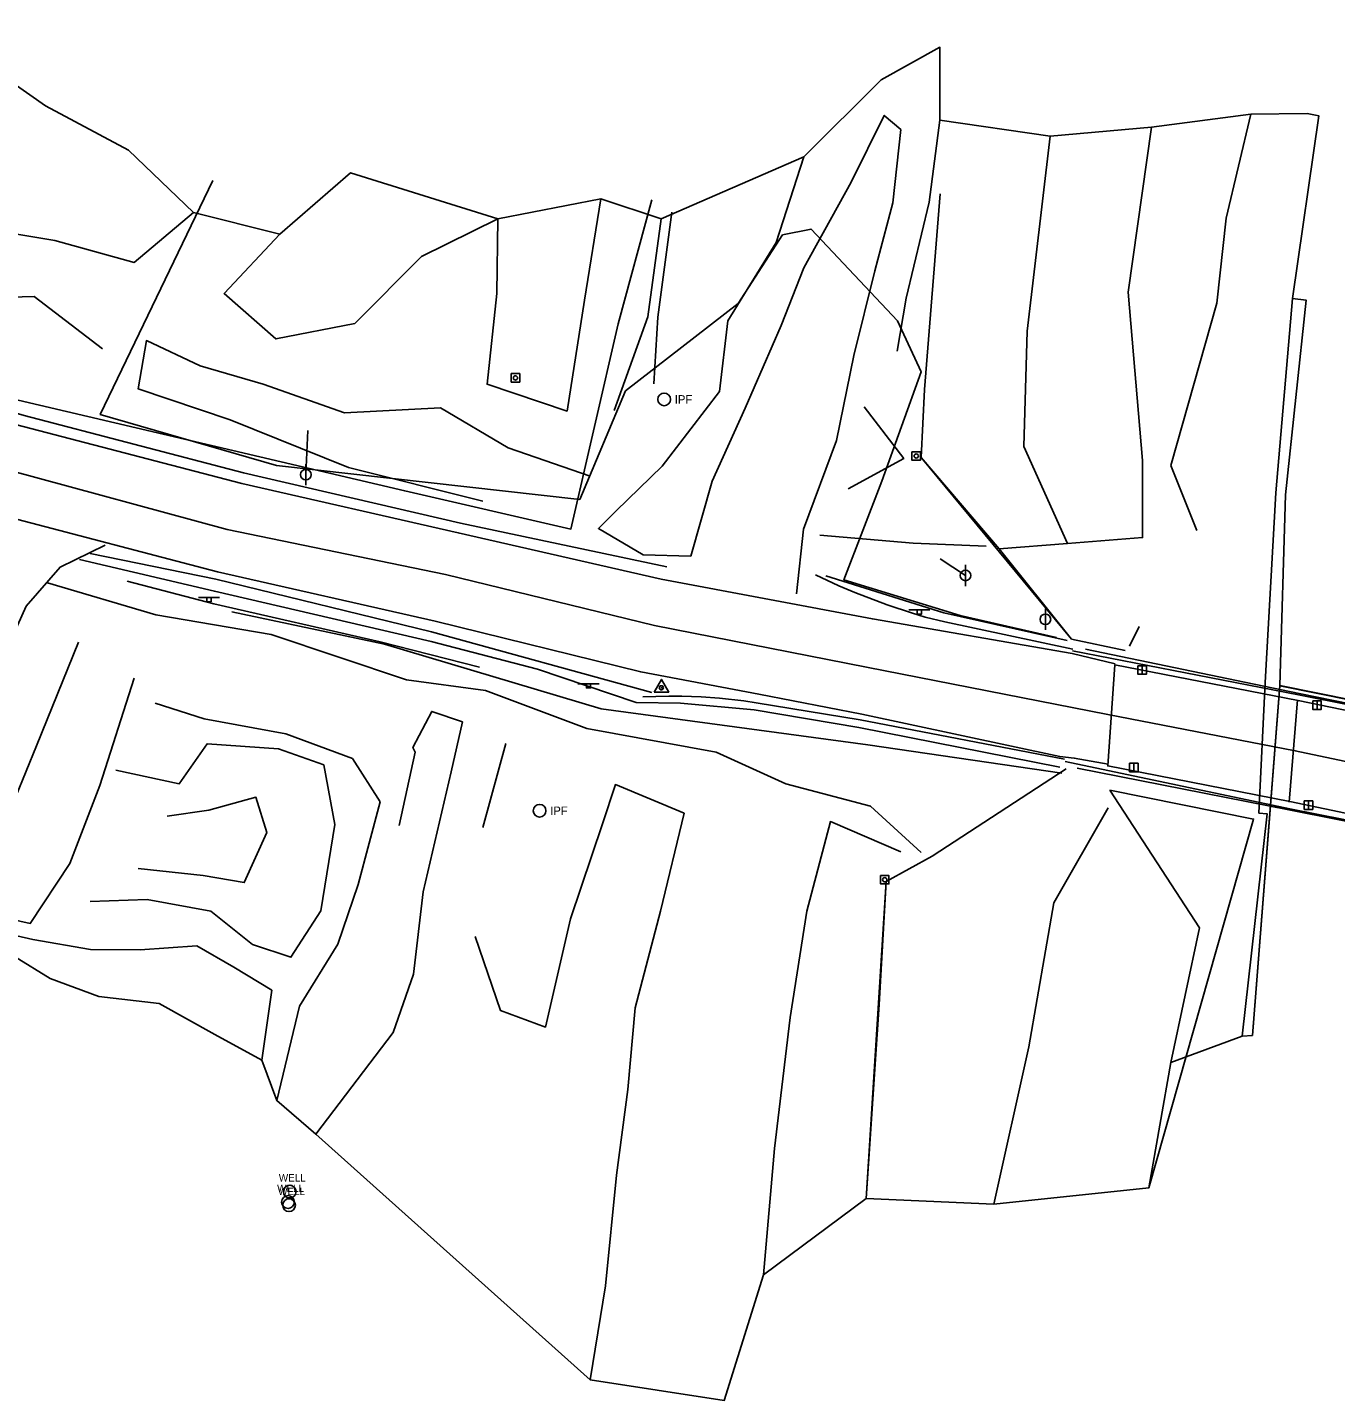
# Model space of a CAD drawing. Extents: x 1158469 to 1165378, y 609843 to 611748.
# Drawn here: x 1159076.5 to 1159385.7, y 611115.2 to 611439.6 of the extents above; entities that cross this region are included whole.
import ezdxf

# ---------------------------------------------------------------- set-up
doc = ezdxf.new("R2010")
doc.units = 0
for name, color, linetype in [('Exterior Boundary', 7, 'Continuous'), ('S_Bridge_Centerline', 7, 'Continuous'), ('S_Bridge_Curb', 7, 'Continuous'), ('S_Bridge_Deck', 7, 'Continuous'), ('S_Bridge_Downspout', 7, 'Continuous'), ('S_Bridge_ExpansionJoint', 7, 'Continuous'), ('S_Bridge_Rail', 7, 'Continuous'), ('S_Control_Temp_Traverse', 7, 'Continuous'), ('S_Fencing_PostAndRail', 7, 'Continuous'), ('S_Fencing_SmoothWire', 7, 'Continuous'), ('S_Ground_Elevation', 7, 'Continuous'), ('S_Guardrail_Beam', 7, 'Continuous'), ('S_Property_IronPipeFound', 7, 'Continuous'), ('S_Property_StoneWall', 7, 'Continuous'), ('S_Property_Well_Top', 7, 'Continuous'), ('S_Roadway_Centerline', 7, 'Continuous'), ('S_Roadway_Drive_Gravel', 7, 'Continuous'), ('S_Roadway_Edge_Pavement', 7, 'Continuous'), ('S_Roadway_Edge_Shoulder', 7, 'Continuous'), ('S_Roadway_Monument', 7, 'Continuous'), ('S_Traffic_Sign_SinglePost', 7, 'Continuous'), ('S_Trees_TreeLine', 7, 'Continuous'), ('S_Utilities_GuyWire3', 7, 'Continuous'), ('S_Utilities_Pole_Power', 7, 'Continuous')]:
    doc.layers.add(name, color=color, linetype=linetype)

msp = doc.modelspace()

# ---------------------------------------------------------------- linework, layer by layer
at = {"layer": 'Exterior Boundary'}
for points in [[(1159635.63, 611231.07), (1159372.54, 611284.19), (1159373.88, 611329.19), (1159378.74, 611375.17), (1159375.51, 611375.57), (1159381.73, 611418.72), (1159378.95, 611419.26), (1159365.66, 611419.16), (1159342.14, 611416.1), (1159318.23, 611413.94), (1159292.11, 611417.69), (1159292.16, 611434.95), (1159278.27, 611427.25), (1159259.97, 611409.07), (1159226.3, 611394.41), (1159212.01, 611399.1), (1159187.7, 611394.43), (1159152.86, 611405.27), (1159136.14, 611390.78), (1159115.73, 611395.93), (1159100.36, 611410.62), (1159080.75, 611421.12), (1159063.46, 611433.13)], [(1159073.44, 611220.14), (1159081.84, 611214.97), (1159093.36, 611210.68), (1159107.63, 611209.01), (1159120.81, 611201.75), (1159131.92, 611195.62), (1159135.4, 611186.08), (1159144.61, 611178.18), (1159209.51, 611120.14), (1159241.16, 611115.24), (1159250.46, 611144.94), (1159274.69, 611162.96), (1159304.93, 611161.65), (1159341.51, 611165.46), (1159346.75, 611195.08), (1159363.61, 611201.34), (1159366.01, 611201.5), (1159370.15, 611253.8), (1159372.54, 611284.09), (1159635.63, 611230.97)]]:
    msp.add_lwpolyline(points, dxfattribs=at)
at = {"layer": 'S_Bridge_Centerline'}
msp.add_lwpolyline([(1159674.63, 611208.05), (1159630.39, 611216.55), (1159573.31, 611228.41), (1159521.47, 611239.25), (1159469.89, 611249.34), (1159423.64, 611258.69), (1159376.15, 611268.75), (1159331.81, 611277.28)], dxfattribs=at)
at = {"layer": 'S_Bridge_Curb'}
for points in [[(1159684.98, 611219.26), (1159631.37, 611230.44), (1159574.28, 611242), (1159524.19, 611252.27), (1159472.87, 611262.36), (1159426.46, 611272.11), (1159376.9, 611281.95), (1159323.48, 611292.34)], [(1159321.73, 611266.19), (1159374.86, 611255.01), (1159420.71, 611245.97), (1159467.38, 611236.47), (1159518.2, 611226.16), (1159571.8, 611215.46), (1159629.11, 611203.69), (1159682.45, 611193.04)]]:
    msp.add_lwpolyline(points, dxfattribs=at)
at = {"layer": 'S_Bridge_Deck'}
msp.add_lwpolyline([(1159674.77, 611220.16), (1159631.33, 611229.06), (1159574.28, 611240.5), (1159523.84, 611250.83), (1159472.5, 611261.22), (1159426.19, 611270.44), (1159376.83, 611280.64), (1159333.47, 611289.01), (1159331.83, 611265.16), (1159374.86, 611256.72), (1159421.1, 611247.09), (1159467.74, 611237.8), (1159518.79, 611227.05), (1159571.91, 611216.77), (1159629.54, 611204.73), (1159672.27, 611196.27)], close=True, dxfattribs=at)
at = {"layer": 'S_Bridge_Downspout'}
for p, q in [((1159339.96, 611288.83), (1159339.96, 611286.83)), ((1159381.29, 611280.52), (1159381.29, 611278.52)), ((1159338, 611265.8), (1159338, 611263.8)), ((1159379.29, 611256.89), (1159379.29, 611254.89))]:
    msp.add_line(p, q, dxfattribs=at)
for points in [[(1159338.96, 611288.83), (1159340.96, 611288.83), (1159340.96, 611286.83), (1159338.96, 611286.83)], [(1159380.29, 611280.52), (1159382.29, 611280.52), (1159382.29, 611278.52), (1159380.29, 611278.52)], [(1159337, 611265.8), (1159339, 611265.8), (1159339, 611263.8), (1159337, 611263.8)], [(1159378.29, 611256.89), (1159380.29, 611256.89), (1159380.29, 611254.89), (1159378.29, 611254.89)]]:
    msp.add_lwpolyline(points, close=True, dxfattribs=at)
at = {"layer": 'S_Bridge_ExpansionJoint'}
msp.add_lwpolyline([(1159374.68, 611256.58), (1159376.7, 611280.78)], dxfattribs=at)
at = {"layer": 'S_Bridge_Rail'}
for points in [[(1159681.77, 611220.75), (1159631.38, 611230.81), (1159574.64, 611242.4), (1159523.8, 611252.53), (1159472.86, 611262.72), (1159426.56, 611272.22), (1159377.08, 611282.26), (1159326.57, 611292.77)], [(1159324.58, 611264.65), (1159374.63, 611254.82), (1159420.65, 611245.67), (1159467.25, 611236.19), (1159518.3, 611225.97), (1159571.68, 611214.96), (1159629.27, 611203.51), (1159679.88, 611193.04)]]:
    msp.add_lwpolyline(points, dxfattribs=at)
at = {"layer": 'S_Control_Temp_Traverse'}
for p, q in [((1159226.19, 611283.61), (1159226.44, 611283.61)), ((1159226.32, 611283.73), (1159226.32, 611283.48))]:
    msp.add_line(p, q, dxfattribs=at)
msp.add_lwpolyline([(1159224.58, 611282.61), (1159228.05, 611282.61), (1159226.32, 611285.61)], close=True, dxfattribs=at)
msp.add_circle((1159226.32, 611283.61), 0.5, dxfattribs=at)
at = {"layer": 'S_Fencing_PostAndRail'}
msp.add_lwpolyline([(1159224.05, 611398.88), (1159216.11, 611369.59), (1159204.94, 611321.1), (1159165.67, 611330.11), (1159067.84, 611353.1)], dxfattribs=at)
at = {"layer": 'S_Fencing_SmoothWire'}
for points in [[(1159292.19, 611400.34), (1159288.5, 611354.05), (1159287.76, 611338.01), (1159323.28, 611295.11)], [(1159322.03, 611264.48), (1159290.33, 611243.83), (1159279.48, 611237.84), (1159274.69, 611162.96)]]:
    msp.add_lwpolyline(points, dxfattribs=at)
at = {"layer": 'S_Ground_Elevation'}
for points in [[(1159094.2, 611363.7), (1159078.09, 611376.08), (1159063.74, 611375.67), (1159054.93, 611372.77), (1159045.87, 611365.49), (1159040.44, 611372.25), (1159048.64, 611395.43), (1159062.07, 611392.76), (1159082.97, 611389.29), (1159101.7, 611384.1), (1159115.73, 611395.93), (1159100.36, 611410.62), (1159080.75, 611421.12), (1159063.46, 611433.13), (1159042.41, 611439.62)], [(1159282.04, 611363.18), (1159284.22, 611375.64), (1159289.65, 611398.37), (1159292.11, 611417.69), (1159292.16, 611434.95), (1159278.27, 611427.25), (1159259.97, 611409.07), (1159253.45, 611388.82), (1159242.03, 611370.3), (1159240.04, 611353.64), (1159226.51, 611335.95), (1159215.63, 611325.43), (1159211.46, 611321.27), (1159222.02, 611315.05), (1159233.31, 611314.7)], [(1159258.28, 611305.78), (1159259.91, 611321.1), (1159267.73, 611342.01), (1159271.81, 611362.1), (1159276.79, 611382.1), (1159281.02, 611398.21), (1159282.9, 611415.49), (1159279.02, 611418.83), (1159271.19, 611403.08), (1159260, 611382.86), (1159254.67, 611369.2), (1159246.14, 611349.71), (1159238.3, 611332.4), (1159233.31, 611314.7)], [(1159365.66, 611419.16), (1159359.83, 611394.56), (1159357.64, 611374.52), (1159346.74, 611336.13), (1159352.85, 611320.78)], [(1159378.95, 611419.26), (1159381.73, 611418.72), (1159375.51, 611375.57), (1159371.52, 611329.69), (1159369.03, 611284.86), (1159367.56, 611254.02), (1159369.48, 611253.85), (1159363.61, 611201.34)], [(1159342.14, 611416.1), (1159336.69, 611377.07), (1159340.02, 611337.34), (1159340.08, 611319.09), (1159322.35, 611317.71)], [(1159318.23, 611413.94), (1159312.79, 611367.87), (1159312, 611340.59), (1159322.35, 611317.71), (1159306.18, 611316.41)], [(1159215.19, 611349.14), (1159223.11, 611371.29), (1159226.3, 611394.41), (1159212.01, 611399.1), (1159208.15, 611375.21), (1159204.02, 611348.99), (1159185.13, 611355.32), (1159187.42, 611376.73), (1159187.7, 611394.43), (1159169.64, 611385.49), (1159153.84, 611369.71), (1159135.2, 611366.05), (1159122.96, 611376.77), (1159136.14, 611390.78), (1159152.86, 611405.27)], [(1159292.19, 611400.34), (1159288.5, 611354.05), (1159287.76, 611338.01), (1159306.18, 611316.41), (1159323.28, 611295.11), (1159335.94, 611292.41)], [(1159378.74, 611375.17), (1159373.88, 611329.19), (1159372.54, 611284.19), (1159366.01, 611201.5)], [(1159209.5, 611333.59), (1159190.12, 611340.29), (1159174.15, 611349.78), (1159151.4, 611348.56), (1159132.19, 611355.36), (1159117.3, 611359.64), (1159104.61, 611365.63), (1159102.69, 611354.24), (1159124.39, 611346.92), (1159152.38, 611335.67), (1159184.13, 611327.68)], [(1159270.47, 611330.64), (1159283.6, 611337.81), (1159274.23, 611350)], [(1159303.09, 611317.09), (1159285.83, 611317.8), (1159263.74, 611319.66)], [(1159320.53, 611264.85), (1159273, 611274.21), (1159248.24, 611278.4), (1159230.83, 611279.99), (1159220.35, 611280.12), (1159197.08, 611287.98), (1159171.94, 611294.57), (1159120.66, 611306.43), (1159088.79, 611313.93)], [(1159287.76, 611244.67), (1159275.75, 611255.65), (1159255.76, 611260.95), (1159239.24, 611268.38), (1159208.7, 611274.03), (1159184.75, 611283.01), (1159166.05, 611285.5), (1159134.1, 611296.19), (1159106.79, 611300.83), (1159081.24, 611308.38)], [(1159100.05, 611308.82), (1159120.53, 611303.47), (1159159.84, 611294.46), (1159183.35, 611288.46)], [(1159322.2, 611294.79), (1159293.09, 611301.3), (1159265.17, 611310.03)], [(1159339.25, 611298.09), (1159337, 611293.46)], [(1159088.54, 611294.39), (1159078.59, 611269.87), (1159071.32, 611251.93), (1159066.24, 611230.4), (1159077.15, 611227.97), (1159086.5, 611242.08), (1159093.61, 611260.5), (1159101.74, 611285.9)], [(1159106.64, 611279.96), (1159118.26, 611276.25), (1159137.59, 611272.76), (1159153.31, 611266.93), (1159159.89, 611256.7), (1159154.62, 611237.16), (1159149.81, 611223.09), (1159140.82, 611208.38), (1159135.4, 611186.08), (1159144.61, 611178.18), (1159162.93, 611202.17), (1159167.71, 611215.96), (1159170.02, 611235.4), (1159176.65, 611263.8), (1159179.31, 611275.57), (1159172.05, 611278.04), (1159167.57, 611269.48), (1159168.14, 611268.39), (1159164.38, 611251.12)], [(1159097.37, 611264.16), (1159112.37, 611260.95), (1159118.93, 611270.34), (1159135.81, 611269.19), (1159146.52, 611265.41), (1159149.13, 611251.31), (1159145.86, 611230.93), (1159138.77, 611219.96), (1159129.68, 611222.99), (1159119.79, 611230.83), (1159104.78, 611233.64), (1159091.31, 611233.15)], [(1159189.56, 611270.46), (1159184.12, 611250.61)], [(1159322.03, 611264.48), (1159290.33, 611243.83), (1159279.48, 611237.84), (1159277.81, 611208.82), (1159274.69, 611162.96)], [(1159182.32, 611224.86), (1159188.31, 611207.37), (1159198.92, 611203.45), (1159204.86, 611229.05), (1159212.41, 611251.5), (1159215.46, 611260.74), (1159231.69, 611253.98), (1159226.12, 611230.87), (1159220.16, 611208.04), (1159218.4, 611188.68), (1159215.75, 611168.47), (1159213.14, 611142.36), (1159209.51, 611120.14), (1159241.16, 611115.24), (1159250.46, 611144.94), (1159253.09, 611174.81), (1159256.78, 611205.71), (1159260.71, 611230.87), (1159266.28, 611252.01), (1159282.92, 611244.83)], [(1159332.32, 611259.4), (1159353.53, 611226.93), (1159346.75, 611195.08), (1159341.51, 611165.46)], [(1159102.63, 611240.92), (1159118.02, 611239.26), (1159127.74, 611237.59), (1159133.04, 611249.46), (1159130.5, 611257.76), (1159119.35, 611254.74), (1159109.53, 611253.3)], [(1159331.92, 611255.25), (1159319.11, 611232.83), (1159313.2, 611198.8), (1159304.93, 611161.65)], [(1159061.85, 611227.81), (1159077.75, 611224.18), (1159091.39, 611221.78), (1159103.11, 611221.71), (1159116.5, 611222.65), (1159125.25, 611217.59), (1159134.28, 611212.15), (1159131.92, 611195.62), (1159120.81, 611201.75), (1159107.63, 611209.01), (1159093.36, 611210.68), (1159081.84, 611214.97), (1159073.44, 611220.14), (1159059.48, 611221.91), (1159048.11, 611222.2)]]:
    msp.add_lwpolyline(points, dxfattribs=at)
at = {"layer": 'S_Guardrail_Beam'}
for points in [[(1159323.61, 611292.74), (1159293.33, 611299.2), (1159288.71, 611300.33), (1159285.67, 611301.21), (1159279.66, 611303.22), (1159272.04, 611306.11), (1159268.29, 611307.69), (1159262.72, 611310.27)], [(1159321.63, 611266.77), (1159273.3, 611276.03), (1159248.71, 611280.06), (1159245.83, 611280.5), (1159240.07, 611281.17), (1159235.74, 611281.49), (1159231.16, 611281.66), (1159228.1, 611281.67), (1159221.97, 611281.45)]]:
    msp.add_lwpolyline(points, dxfattribs=at)
at = {"layer": 'S_Property_IronPipeFound'}
for centre in [(1159226.98, 611351.75), (1159197.53, 611254.56)]:
    msp.add_circle(centre, 1.5, dxfattribs=at)
at = {"layer": 'S_Property_StoneWall'}
msp.add_lwpolyline([(1159224.55, 611355.41), (1159225.5, 611371.14), (1159228.78, 611395.97)], dxfattribs=at)
at = {"layer": 'S_Property_Well_Top'}
for centre in [(1159138.48, 611164.61), (1159138.07, 611162.14), (1159138.32, 611161.39)]:
    msp.add_circle(centre, 1.5, dxfattribs=at)
at = {"layer": 'S_Roadway_Centerline'}
msp.add_lwpolyline([(1159331.81, 611277.28), (1159274.84, 611288.49), (1159224.73, 611298.33), (1159175.26, 611310.41), (1159123.67, 611320.98), (1159072.1, 611335.03), (1159024.95, 611346.83), (1158973.61, 611362.21), (1158923.32, 611376.81), (1158917.59, 611378.51), (1158906.21, 611382.09)], dxfattribs=at)
at = {"layer": 'S_Roadway_Drive_Gravel'}
msp.add_lwpolyline([(1159052.56, 611229.45), (1159059.49, 611248.82), (1159063.99, 611269.11), (1159066.47, 611281.51), (1159076.22, 611302.93), (1159084.19, 611312.09), (1159094.89, 611317.34)], dxfattribs=at)
at = {"layer": 'S_Roadway_Edge_Pavement'}
for points in [[(1159333.57, 611289.26), (1159323.43, 611291.71), (1159276.2, 611299.9), (1159226.25, 611309.31), (1159178.31, 611320.23), (1159127.18, 611331.87), (1159075.46, 611345.32), (1159027.63, 611357.79), (1158976.91, 611372.12), (1158924.82, 611387.65), (1158910.66, 611392.01), (1158903.63, 611394.28)], [(1159331.91, 611265.57), (1159323.93, 611267.01), (1159320.48, 611267.38), (1159273.69, 611277.35), (1159249.33, 611282.09), (1159221.46, 611287.37), (1159172.87, 611299.32), (1159121.37, 611311.03), (1159070.91, 611324.22), (1159022.32, 611336.86), (1158967.91, 611352.37), (1158922.03, 611366.05), (1158906.33, 611370.96)]]:
    msp.add_lwpolyline(points, dxfattribs=at)
at = {"layer": 'S_Roadway_Edge_Shoulder'}
for points in [[(1159227.63, 611312.2), (1159178.87, 611322.51), (1159127.52, 611334.43), (1159075.72, 611347.92), (1159028.86, 611361.42), (1158977.58, 611373.79)], [(1159224.05, 611282.48), (1159171.99, 611296.82), (1159121.02, 611309.27), (1159091.28, 611315.37)]]:
    msp.add_lwpolyline(points, dxfattribs=at)
at = {"layer": 'S_Roadway_Monument'}
for points in [[(1159190.84, 611357.83), (1159192.84, 611357.83), (1159192.84, 611355.83), (1159190.84, 611355.83)], [(1159285.56, 611339.38), (1159287.56, 611339.38), (1159287.56, 611337.38), (1159285.56, 611337.38)], [(1159278.12, 611239.27), (1159280.12, 611239.27), (1159280.12, 611237.27), (1159278.12, 611237.27)]]:
    msp.add_lwpolyline(points, close=True, dxfattribs=at)
for centre in [(1159191.84, 611356.83), (1159286.56, 611338.38), (1159279.12, 611238.27)]:
    msp.add_circle(centre, 0.5, dxfattribs=at)
at = {"layer": 'S_Traffic_Sign_SinglePost'}
for p, q in [((1159116.9, 611304.93), (1159121.9, 611304.93)), ((1159284.8, 611302), (1159289.8, 611302)), ((1159206.59, 611284.59), (1159211.59, 611284.59))]:
    msp.add_line(p, q, dxfattribs=at)
for points in [[(1159118.9, 611304.93), (1159119.9, 611304.93), (1159119.9, 611303.93), (1159118.9, 611303.93)], [(1159286.8, 611302), (1159287.8, 611302), (1159287.8, 611301), (1159286.8, 611301)], [(1159208.59, 611284.59), (1159209.59, 611284.59), (1159209.59, 611283.59), (1159208.59, 611283.59)]]:
    msp.add_lwpolyline(points, close=True, dxfattribs=at)
at = {"layer": 'S_Trees_TreeLine'}
for points in [[(1159319.71, 611295.51), (1159296.93, 611300.71), (1159269.47, 611309.13), (1159278.45, 611332.44), (1159287.71, 611358.28), (1159282.14, 611370.33), (1159261.7, 611392), (1159254.98, 611390.62), (1159244.5, 611374.39), (1159217.82, 611353.76), (1159207.03, 611328.1), (1159135.34, 611336.1), (1159093.68, 611348.2), (1159120.33, 611403.44)], [(1159321.01, 611263.45), (1159275.14, 611270.18), (1159212.07, 611278.65), (1159160.9, 611293.95), (1159124.78, 611301.59)], [(1159332.32, 611259.4), (1159366.3, 611252.61), (1159341.51, 611165.46)]]:
    msp.add_lwpolyline(points, dxfattribs=at)
at = {"layer": 'S_Utilities_GuyWire3'}
for points in [[(1159142.28, 611333.98), (1159142.76, 611344.38)], [(1159298.2, 611310.16), (1159292.23, 611314.09)]]:
    msp.add_lwpolyline(points, dxfattribs=at)
at = {"layer": 'S_Utilities_Pole_Power'}
for p, q in [((1159142.28, 611336.48), (1159142.28, 611331.48)), ((1159298.2, 611312.66), (1159298.2, 611307.66)), ((1159317.09, 611302.29), (1159317.09, 611297.29))]:
    msp.add_line(p, q, dxfattribs=at)
for centre in [(1159142.28, 611333.98), (1159298.2, 611310.16), (1159317.09, 611299.79)]:
    msp.add_circle(centre, 1.25, dxfattribs=at)

# ---------------------------------------------------------------- texts
at = {"layer": 'S_Property_IronPipeFound'}
for p in [(1159229.48, 611350.75), (1159200.03, 611253.56)]:
    msp.add_text('IPF', height=2, dxfattribs=at).set_placement(p)
at = {"layer": 'S_Property_Well_Top'}
for p in [(1159135.9, 611166.98), (1159135.49, 611164.52), (1159135.74, 611163.76)]:
    msp.add_text('WELL', height=1.75, rotation=360, dxfattribs=at).set_placement(p)

doc.saveas('drawing.dxf')
